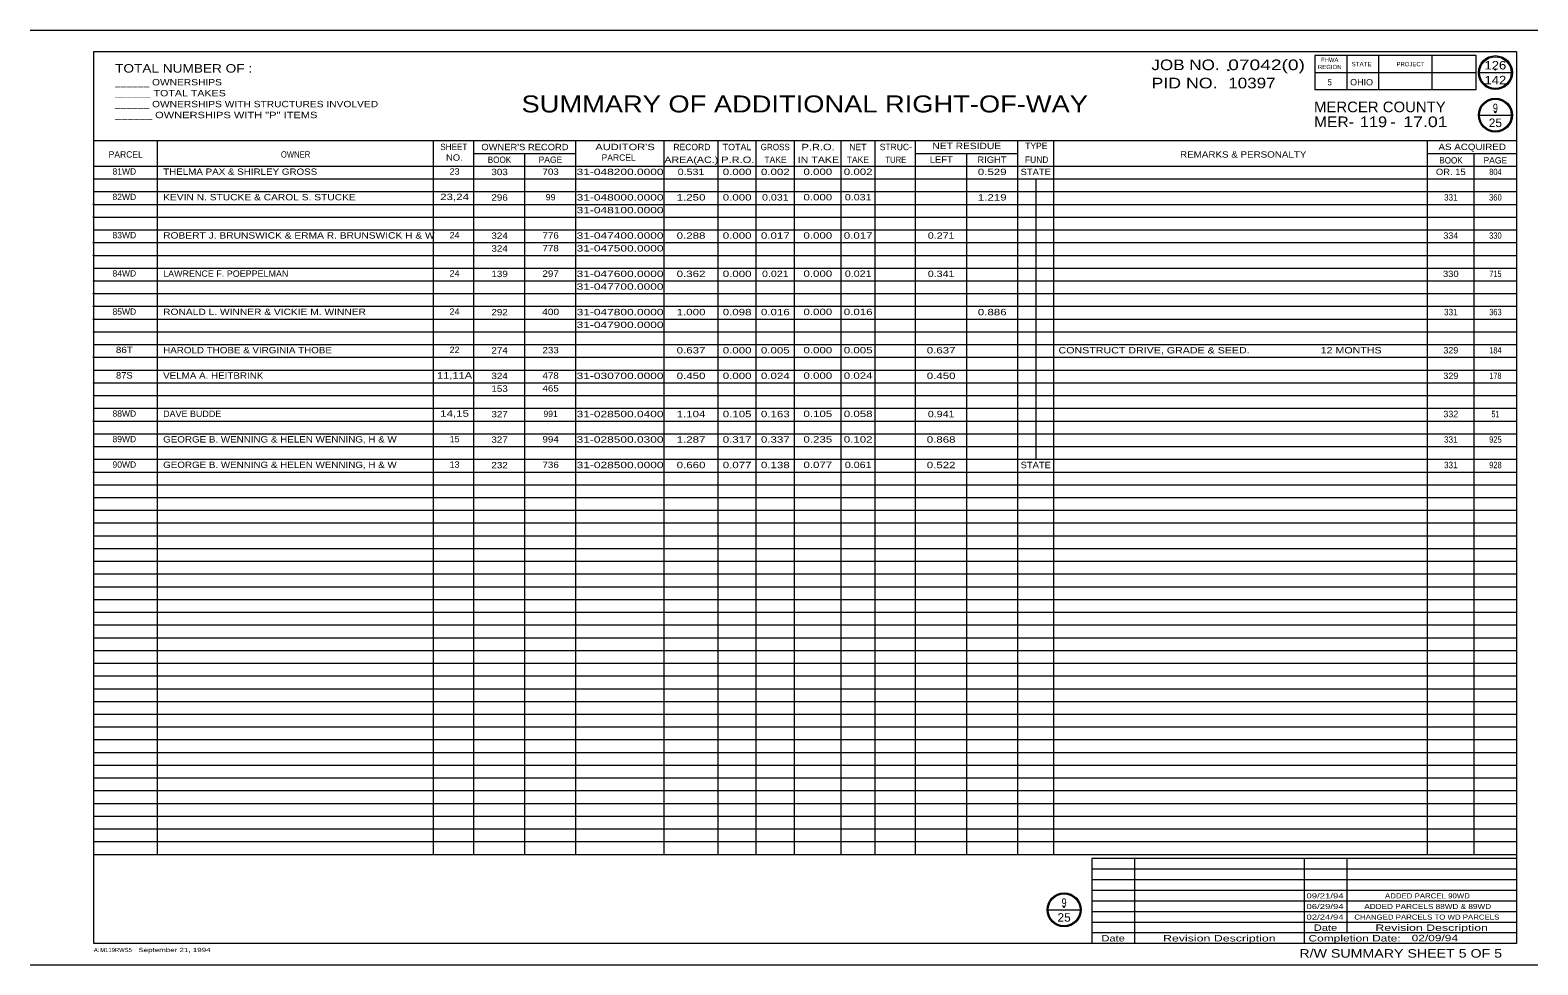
# Model space of a CAD drawing. Extents: x -1 to 34.5, y 0 to 22.
import ezdxf
from ezdxf.enums import TextEntityAlignment as Align

# ---------------------------------------------------------------- set-up
doc = ezdxf.new("R2010")
doc.units = 0
doc.header["$LTSCALE"] = 0.06
doc.header["$PDMODE"] = 32
doc.header["$PDSIZE"] = 0.03
doc.layers.add('1', color=7, linetype='Continuous', lineweight=13)
doc.layers.add('60', color=7, linetype='Continuous', lineweight=13)
doc.layers.add('16', color=7, linetype='Continuous')

msp = doc.modelspace()

# ---------------------------------------------------------------- linework, layer by layer
at = {"layer": '1'}
msp.add_line((22.67942, 18.49667), (22.67942, 11.9), dxfattribs=at)
for p in [(27.21, 21.05892), (33.5, 21.07425), (33.5, 20.07), (0.5, 18.5), (0.5, 17.9), (0.5, 17.6), (0.5, 17), (0.5, 16.7), (0.5, 16.1), (0.5, 15.8), (0.5, 15.5), (0.5, 15.2), (0.5, 14.9), (0.5, 14.3), (0.5, 13.7), (0.5, 13.4), (0.5, 12.8), (0.5, 12.2), (0.5, 11.6), (23.345, 1.36508)]:
    msp.add_point(p, dxfattribs=at)
at = {"layer": '60'}
for p, q in [((-1, 22), (34.5, 22)), ((0.5, 21.5), (34, 21.5)), ((0.5, 0.5), (0.5, 21.5)), ((30, 21.4), (30, 20.6)), ((30.75, 21.4), (30.75, 20.6)), ((32.002, 21.4), (32.002, 20.6)), ((29.25, 21), (33.05, 21)), ((33.125, 21), (33.875, 21)), ((33.125, 20.00258), (33.875, 20.00258)), ((0.5, 19.4), (34, 19.4)), ((2, 2.6), (2, 19.4)), ((8.5, 2.6), (8.5, 19.4)), ((9.45025, 2.6), (9.45025, 19.4)), ((11.85025, 2.6), (11.85025, 19.4)), ((13.92625, 2.6), (13.92625, 19.4)), ((15.19617, 2.6), (15.19617, 19.4)), ((16.09617, 2.6), (16.09617, 19.4)), ((16.99617, 2.6), (16.99617, 19.4)), ((18.09617, 2.6), (18.09617, 19.4)), ((18.89617, 2.6), (18.89617, 19.4)), ((19.84617, 2.6), (19.84617, 19.4)), ((22.253, 2.6), (22.253, 19.4)), ((23.103, 2.6), (23.103, 19.4)), ((31.90092, 2.6), (31.90092, 19.4)), ((9.45025, 19.1), (11.85025, 19.1)), ((10.65025, 2.6), (10.65025, 19.1)), ((19.853, 19.1), (22.253, 19.1)), ((21.053, 2.6), (21.053, 19.1)), ((31.90092, 19.1), (34, 19.1)), ((33.00092, 2.6), (33.00092, 19.1)), ((0.5, 18.8), (34, 18.8)), ((0.5, 18.5), (34, 18.5)), ((0.5, 18.2), (34, 18.2)), ((0.5, 17.9), (34, 17.9)), ((0.5, 17.6), (34, 17.6)), ((0.5, 17.3), (34, 17.3)), ((0.5, 17), (34, 17)), ((0.5, 16.7), (34, 16.7)), ((0.5, 16.4), (34, 16.4)), ((0.5, 16.1), (34, 16.1)), ((0.5, 15.8), (34, 15.8)), ((0.5, 15.5), (34, 15.5)), ((0.5, 15.2), (34, 15.2)), ((0.5, 14.9), (34, 14.9)), ((0.5, 14.6), (34, 14.6)), ((0.5, 14.3), (34, 14.3)), ((0.5, 14), (34, 14)), ((0.5, 13.7), (34, 13.7)), ((0.5, 13.4), (34, 13.4)), ((0.5, 13.1), (34, 13.1)), ((0.5, 12.8), (34, 12.8)), ((0.5, 12.5), (34, 12.5)), ((0.5, 12.2), (34, 12.2)), ((0.5, 11.9), (34, 11.9)), ((0.5, 11.6), (34, 11.6)), ((0.5, 11.3), (34, 11.3)), ((0.5, 11), (34, 11)), ((0.5, 10.7), (34, 10.7)), ((0.5, 10.4), (34, 10.4)), ((0.5, 10.1), (34, 10.1)), ((0.5, 9.8), (34, 9.8)), ((0.5, 9.5), (34, 9.5)), ((0.5, 9.2), (34, 9.2)), ((0.5, 8.9), (34, 8.9)), ((0.5, 8.6), (34, 8.6)), ((0.5, 8.3), (34, 8.3)), ((0.5, 8), (34, 8)), ((0.5, 7.7), (34, 7.7)), ((0.5, 7.4), (34, 7.4)), ((0.5, 7.1), (34, 7.1)), ((0.5, 6.8), (34, 6.8)), ((0.5, 6.5), (34, 6.5)), ((0.5, 6.2), (34, 6.2)), ((0.5, 5.9), (34, 5.9)), ((0.5, 5.6), (34, 5.6)), ((0.5, 5.3), (34, 5.3)), ((0.5, 5), (34, 5)), ((0.5, 4.7), (34, 4.7)), ((0.5, 4.4), (34, 4.4)), ((0.5, 4.1), (34, 4.1)), ((0.5, 3.8), (34, 3.8)), ((0.5, 3.5), (34, 3.5)), ((0.5, 3.2), (34, 3.2)), ((0.5, 2.9), (34, 2.9)), ((0.5, 2.6), (34, 2.6)), ((34, 2.5), (24, 2.5)), ((24, 2.5), (24, 0.5)), ((25, 2.5), (25, 0.5)), ((29, 2.5), (29, 0.5)), ((30, 2.5), (30, 0.75)), ((34, 2.25), (24, 2.25)), ((34, 2), (24, 2)), ((34, 1.75), (24, 1.75)), ((34, 1.5), (24, 1.5)), ((22.97, 1.29767), (23.72, 1.29767)), ((34, 1.25), (24, 1.25)), ((34, 1), (24, 1)), ((34, 0.75), (24, 0.75)), ((-1, 0), (34.5, 0))]:
    msp.add_line(p, q, dxfattribs=at)
msp.add_lwpolyline([(34, 21.5), (34, 0.5), (0.5, 0.5)], dxfattribs=at)
msp.add_lwpolyline([(29.25, 20.6), (33.05, 20.6), (33.05, 21.4), (29.25, 21.4)], close=True, dxfattribs=at)
for centre, radius in [((33.5, 21), 0.4), ((33.5, 21), 0.375), ((33.5, 20), 0.4), ((33.5, 20), 0.375), ((23.34498, 1.2951), 0.4), ((23.34498, 1.2951), 0.375)]:
    msp.add_circle(centre, radius, dxfattribs=at)

# ---------------------------------------------------------------- texts
at = {"layer": '1'}
for s, height, width, p in [('MERCER COUNTY', 0.25, 1.05, (29.22958, 20.06792)), ('MER-', 0.25, 1.1, (29.22958, 19.71792)), ('17.01', 0.25, 1.25, (31.32958, 19.71792)), ('-', 0.25, 1.1, (31.02958, 19.71792)), ('THELMA PAX & SHIRLEY GROSS', 0.15, 1.15, (2.13167, 18.59433)), ('KEVIN N. STUCKE & CAROL S. STUCKE ', 0.15, 1.2, (2.13167, 17.99433)), ('ROBERT J. BRUNSWICK & ERMA R. BRUNSWICK H & W', 0.15, 1.2, (2.13167, 17.09433)), ('LAWRENCE F. POEPPELMAN', 0.15, 1.05, (2.13167, 16.19433)), ('RONALD L. WINNER & VICKIE M. WINNER', 0.15, 1.2, (2.13167, 15.29433)), ('HAROLD THOBE & VIRGINIA THOBE', 0.15, 1.15, (2.13167, 14.39433)), ('CONSTRUCT DRIVE, GRADE & SEED.                        12 MONTHS', 0.15, 1.25, (23.21425, 14.39067)), ('VELMA A. HEITBRINK', 0.15, 1.15, (2.13167, 13.79433)), ('DAVE BUDDE', 0.15, 1.05, (2.13167, 12.89433)), ('GEORGE B. WENNING & HELEN WENNING, H & W', 0.15, 1.15, (2.13167, 12.29433)), ('GEORGE B. WENNING & HELEN WENNING, H & W', 0.15, 1.15, (2.13167, 11.69433)), ('09/21/94', 0.12, 1.4, (29.05167, 1.5635)), ('06/29/94', 0.12, 1.4, (29.05167, 1.3135)), ('ADDED PARCELS 88WD & 89WD', 0.12, 1.2, (30.41417, 1.3135)), ('ADDED PARCEL 90WD', 0.12, 1.15, (30.90058, 1.5635)), ('02/24/94', 0.12, 1.4, (29.05167, 1.0635)), ('CHANGED PARCELS TO WD PARCELS', 0.12, 1.15, (30.17933, 1.0635)), ('02/09/94', 0.15, 1.4, (31.52817, 0.55625)), ('September 21, 1994', 0.1, 1.4, (1.55, 0.3))]:
    msp.add_text(s, height=height, dxfattribs=dict(at, width=width)).set_placement(p)
for s, height, width, p in [('119', 0.25, 1.15, (30.62958, 19.71792)), ('23', 0.15, 1.05, (8.9935, 18.60025)), ('303', 0.15, 1.15, (10.05379, 18.5875)), ('703', 0.15, 1.15, (11.25512, 18.59383)), ('31-048200.0000', 0.15, 1.4, (12.89025, 18.59)), ('0.531', 0.15, 1.25, (14.56125, 18.59)), ('0.000', 0.15, 1.35, (15.64621, 18.59)), ('0.002', 0.15, 1.35, (16.54612, 18.59)), ('0.000', 0.15, 1.35, (17.54621, 18.59317)), ('0.002', 0.15, 1.35, (18.49612, 18.59317)), ('0.529', 0.15, 1.35, (21.65296, 18.59)), ('STATE', 0.15, 1.1, (22.678, 18.59)), ('OR. 15', 0.15, 1.1, (32.45092, 18.59)), ('804', 0.15, 0.85, (33.50092, 18.59)), ('23,24', 0.15, 1.35, (8.99346, 18.00025)), ('296', 0.15, 1.15, (10.05387, 17.9875)), ('99', 0.15, 1.05, (11.25517, 17.99383)), ('31-048000.0000', 0.15, 1.4, (12.89025, 17.99)), ('1.250', 0.15, 1.35, (14.56129, 17.99)), ('0.000', 0.15, 1.35, (15.64621, 17.99)), ('0.031', 0.15, 1.25, (16.54617, 17.99)), ('0.000', 0.15, 1.35, (17.54621, 17.99317)), ('0.031', 0.15, 1.25, (18.49617, 17.99317)), ('1.219', 0.15, 1.35, (21.65296, 17.99)), ('331', 0.15, 0.95, (32.45092, 17.99)), ('360', 0.15, 0.9, (33.50092, 17.99)), ('31-048100.0000', 0.15, 1.4, (12.89025, 17.69)), ('24', 0.15, 1.05, (8.9935, 17.10025)), ('324', 0.15, 1.15, (10.05379, 17.0875)), ('776', 0.15, 1.15, (11.25521, 17.09383)), ('31-047400.0000', 0.15, 1.4, (12.89025, 17.09)), ('0.288', 0.15, 1.35, (14.56121, 17.09)), ('0.000', 0.15, 1.35, (15.64621, 17.09)), ('0.017', 0.15, 1.35, (16.54612, 17.09)), ('0.000', 0.15, 1.35, (17.54621, 17.09317)), ('0.017', 0.15, 1.35, (18.49612, 17.09317)), ('0.271', 0.15, 1.25, (20.44967, 17.09)), ('334', 0.15, 1.05, (32.45087, 17.09)), ('330', 0.15, 0.85, (33.50092, 17.09)), ('324', 0.15, 1.15, (10.05379, 16.7875)), ('778', 0.15, 1.15, (11.25512, 16.79383)), ('31-047500.0000', 0.15, 1.4, (12.89025, 16.79)), ('24', 0.15, 1.05, (8.9935, 16.20025)), ('139', 0.15, 1.15, (10.05379, 16.1875)), ('297', 0.15, 1.15, (11.25512, 16.19383)), ('31-047600.0000', 0.15, 1.4, (12.89025, 16.19)), ('0.362', 0.15, 1.35, (14.56121, 16.19)), ('0.000', 0.15, 1.35, (15.64621, 16.19)), ('0.021', 0.15, 1.25, (16.54617, 16.19)), ('0.000', 0.15, 1.35, (17.54621, 16.19317)), ('0.021', 0.15, 1.25, (18.49617, 16.19317)), ('0.341', 0.15, 1.25, (20.44967, 16.19)), ('330', 0.15, 1.1, (32.45087, 16.19)), ('715', 0.15, 0.75, (33.50092, 16.19)), ('31-047700.0000', 0.15, 1.4, (12.89025, 15.89)), ('24', 0.15, 1.05, (8.9935, 15.30025)), ('292', 0.15, 1.15, (10.05379, 15.2875)), ('400', 0.15, 1.2, (11.25521, 15.29383)), ('31-047800.0000', 0.15, 1.4, (12.89025, 15.29)), ('1.000', 0.15, 1.35, (14.56129, 15.29)), ('0.098', 0.15, 1.35, (15.64612, 15.29)), ('0.016', 0.15, 1.35, (16.54621, 15.29)), ('0.000', 0.15, 1.35, (17.54621, 15.29317)), ('0.016', 0.15, 1.35, (18.49621, 15.29317)), ('0.886', 0.15, 1.35, (21.65304, 15.29)), ('331', 0.15, 0.95, (32.45092, 15.29)), ('363', 0.15, 0.85, (33.50096, 15.29)), ('31-047900.0000', 0.15, 1.4, (12.89025, 14.99)), ('86T', 0.15, 1.15, (1.21771, 14.40025)), ('22', 0.15, 1.05, (8.9935, 14.40025)), ('274', 0.15, 1.15, (10.05379, 14.3875)), ('233', 0.15, 1.15, (11.25512, 14.39383)), ('0.637', 0.15, 1.35, (14.56121, 14.39)), ('0.000', 0.15, 1.35, (15.64621, 14.39)), ('0.005', 0.15, 1.35, (16.54612, 14.39)), ('0.000', 0.15, 1.35, (17.54621, 14.39317)), ('0.005', 0.15, 1.35, (18.49612, 14.39317)), ('0.637', 0.15, 1.35, (20.44963, 14.39)), ('329', 0.15, 1.05, (32.45096, 14.39)), ('184', 0.15, 0.75, (33.50092, 14.39)), ('87S', 0.15, 1.1, (1.21767, 13.80025)), ('11,11A', 0.15, 1.3, (8.99346, 13.80025)), ('324', 0.15, 1.15, (10.05379, 13.7875)), ('478', 0.15, 1.15, (11.25512, 13.79383)), ('31-030700.0000', 0.15, 1.4, (12.89025, 13.79)), ('0.450', 0.15, 1.35, (14.56129, 13.79)), ('0.000', 0.15, 1.35, (15.64621, 13.79)), ('0.024', 0.15, 1.35, (16.54612, 13.79)), ('0.000', 0.15, 1.35, (17.54621, 13.79317)), ('0.024', 0.15, 1.35, (18.49612, 13.79317)), ('0.450', 0.15, 1.35, (20.44971, 13.79)), ('329', 0.15, 1.05, (32.45096, 13.79)), ('178', 0.15, 0.75, (33.50092, 13.79)), ('153', 0.15, 1.15, (10.05379, 13.4875)), ('465', 0.15, 1.15, (11.25512, 13.49383)), ('14,15', 0.15, 1.35, (8.99346, 12.90025)), ('327', 0.15, 1.15, (10.05379, 12.8875)), ('31-028500.0400', 0.15, 1.4, (12.89025, 12.89)), ('1.104', 0.15, 1.35, (14.56121, 12.89)), ('0.105', 0.15, 1.35, (15.64612, 12.89)), ('0.163', 0.15, 1.35, (16.54612, 12.89)), ('0.105', 0.15, 1.35, (17.54612, 12.89317)), ('0.058', 0.15, 1.35, (18.49612, 12.89317)), ('0.941', 0.15, 1.25, (20.44967, 12.89)), ('332', 0.15, 1.05, (32.45087, 12.89)), ('51', 0.15, 0.65, (33.50096, 12.89)), ('15', 0.15, 1.05, (8.9935, 12.30025)), ('327', 0.15, 1.15, (10.05379, 12.2875)), ('994', 0.15, 1.15, (11.25512, 12.29383)), ('31-028500.0300', 0.15, 1.4, (12.89025, 12.29)), ('1.287', 0.15, 1.35, (14.56121, 12.29)), ('0.317', 0.15, 1.35, (15.64612, 12.29)), ('0.337', 0.15, 1.35, (16.54612, 12.29)), ('0.235', 0.15, 1.35, (17.54612, 12.29317)), ('0.102', 0.15, 1.35, (18.49612, 12.29317)), ('0.868', 0.15, 1.35, (20.44963, 12.29)), ('331', 0.15, 0.95, (32.45092, 12.29)), ('925', 0.15, 0.85, (33.50096, 12.29)), ('13', 0.15, 1.05, (8.9935, 11.70025)), ('232', 0.15, 1.15, (10.05379, 11.6875)), ('736', 0.15, 1.15, (11.25521, 11.69383)), ('31-028500.0000', 0.15, 1.4, (12.89025, 11.69)), ('0.660', 0.15, 1.35, (14.56129, 11.69)), ('0.077', 0.15, 1.35, (15.64612, 11.69)), ('0.138', 0.15, 1.35, (16.54612, 11.69)), ('0.077', 0.15, 1.35, (17.54612, 11.69317)), ('0.061', 0.15, 1.25, (18.49617, 11.69317)), ('0.522', 0.15, 1.35, (20.44963, 11.69)), ('STATE', 0.15, 1.1, (22.678, 11.69)), ('331', 0.15, 0.95, (32.45092, 11.69)), ('928', 0.15, 0.85, (33.50096, 11.69))]:
    msp.add_text(s, height=height, dxfattribs=dict(at, width=width)).set_placement(p, align=Align.CENTER)
for s, p in [('81WD', (1.21762, 18.60025)), ('82WD', (1.21762, 18.00025)), ('83WD', (1.21762, 17.10025)), ('84WD', (1.21762, 16.20025)), ('85WD', (1.21762, 15.30025)), ('88WD', (1.21762, 12.90025)), ('991', (11.25517, 12.89383)), ('89WD', (1.21762, 12.30025)), ('90WD', (1.21762, 11.70025))]:
    msp.add_text(s, height=0.15, dxfattribs=at).set_placement(p, align=Align.CENTER)
for s, p in [('A:', (0.5, 0.3)), ('M119RWS5', (0.65, 0.3))]:
    msp.add_text(s, height=0.1, dxfattribs=at).set_placement(p)
at = {"layer": '16'}
for s, width, p in [('07042(0)', 1.35, (27.21, 21.05892)), ('10397', 1.2, (27.21, 20.63033))]:
    msp.add_text(s, height=0.25, dxfattribs=dict(at, width=width)).set_placement(p)
for s, width, p in [('126', 1.15, (33.50004, 21.07425)), ('142', 1.15, (33.5, 20.72425)), ('9', 0.8, (33.5, 20.07)), ('25', 1.05, (33.49996, 19.72)), ('9', 0.8, (23.345, 1.36508)), ('25', 1.05, (23.34496, 1.01508))]:
    msp.add_text(s, height=0.2, dxfattribs=dict(at, width=width)).set_placement(p, align=Align.CENTER)
at = {"layer": '60'}
for s, height, width, p in [('JOB NO.', 0.25, 1.2, (25.40233, 21.05892)), ('TOTAL NUMBER OF :', 0.2, 1.2, (1, 21)), ('______ TOTAL TAKES', 0.15, 1.25, (1, 20.44283)), ('______ OWNERSHIPS', 0.15, 1.2, (1, 20.7)), ('PID NO.', 0.25, 1.25, (25.40233, 20.63033)), ('______ OWNERSHIPS WITH STRUCTURES INVOLVED', 0.15, 1.2, (1, 20.18575)), ('______ OWNERSHIPS WITH "P" ITEMS', 0.15, 1.3, (1, 19.92858)), ("AUDITOR'S ", 0.15, 1.3, (12.30883, 19.176)), (' NO.', 0.15, 1.1, (8.73083, 18.92683)), ('TURE', 0.15, 0.9, (19.13825, 18.87483)), ('Completion Date:', 0.15, 1.4, (29.1, 0.55))]:
    msp.add_text(s, height=height, dxfattribs=dict(at, width=width)).set_placement(p)
for s, height, width, p in [('FHWA', 0.1, 0.95, (29.60004, 21.25)), ('REGION', 0.1, 1.05, (29.6, 21.08333)), ('STATE', 0.1, 1.1, (30.35, 21.15)), ('PROJECT', 0.1, 1.05, (31.50004, 21.15)), ('5', 0.15, 0.8, (29.6, 20.7)), ('OHIO', 0.15, 1.05, (30.35004, 20.7)), ('SUMMARY OF ADDITIONAL RIGHT-OF-WAY', 0.4, 1.2, (17.2385, 20.06342)), ('SHEET', 0.15, 0.95, (8.97467, 19.17683)), ("OWNER'S RECORD", 0.15, 1.1, (10.65025, 19.175)), ('TOTAL', 0.15, 1.05, (15.64387, 19.175)), ('GROSS', 0.15, 0.95, (16.54367, 19.175)), ('P.R.O.', 0.15, 1.3, (17.55308, 19.175)), ('NET RESIDUE', 0.15, 1.2, (21.05304, 19.2)), ('AS ACQUIRED', 0.15, 1.15, (32.95442, 19.17858)), ('OWNER', 0.15, 0.9, (5.25004, 19)), ('BOOK', 0.15, 0.95, (10.05029, 18.875)), ('AREA(AC.)', 0.15, 1.25, (14.56738, 18.875)), ('P.R.O.', 0.15, 1.3, (15.66092, 18.875)), ('IN TAKE', 0.15, 1.25, (17.56058, 18.875)), ('LEFT', 0.15, 1.1, (20.45296, 18.87867)), ('RIGHT', 0.15, 1.1, (21.64696, 18.87642)), ('REMARKS & PERSONALTY', 0.15, 1.15, (27.56296, 19)), ('BOOK', 0.15, 0.95, (32.45529, 18.86167)), ('Date', 0.15, 1.3, (29.5, 0.8)), ('Revision Description', 0.15, 1.45, (32, 0.8)), ('Date', 0.15, 1.3, (24.5, 0.55)), ('Revision Description', 0.15, 1.45, (27, 0.55))]:
    msp.add_text(s, height=height, dxfattribs=dict(at, width=width)).set_placement(p, align=Align.CENTER)
for s, p in [('RECORD', (14.58121, 19.175)), ('NET', (18.48912, 19.175)), ('STRUC-', (19.38237, 19.17558)), ('TYPE', (22.691, 19.2)), ('PARCEL', (1.25004, 19)), ('PAGE', (11.25025, 18.875)), ('TAKE', (16.55008, 18.875)), ('TAKE', (18.48908, 18.875)), ('FUND', (22.69962, 18.87642)), ('PAGE', (33.49883, 18.86167))]:
    msp.add_text(s, height=0.15, dxfattribs=at).set_placement(p, align=Align.CENTER)
msp.add_text('PARCEL', height=0.15, dxfattribs=at).set_placement((12.45575, 18.926))
at = {"layer": '60', "width": 1.25}
msp.add_text('R/W SUMMARY SHEET 5 OF 5', height=0.2, dxfattribs=at).set_placement((33.65833, 0.16892), align=Align.RIGHT)

doc.saveas('drawing.dxf')
